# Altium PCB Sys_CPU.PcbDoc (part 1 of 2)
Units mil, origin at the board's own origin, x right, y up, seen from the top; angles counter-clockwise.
Board outline 2999.97 x 2496.97 mil, 4 copper layers (Top Layer, GND, POWER, Bottom Layer); 73 components, 87 nets, 428 pads, 131 vias.
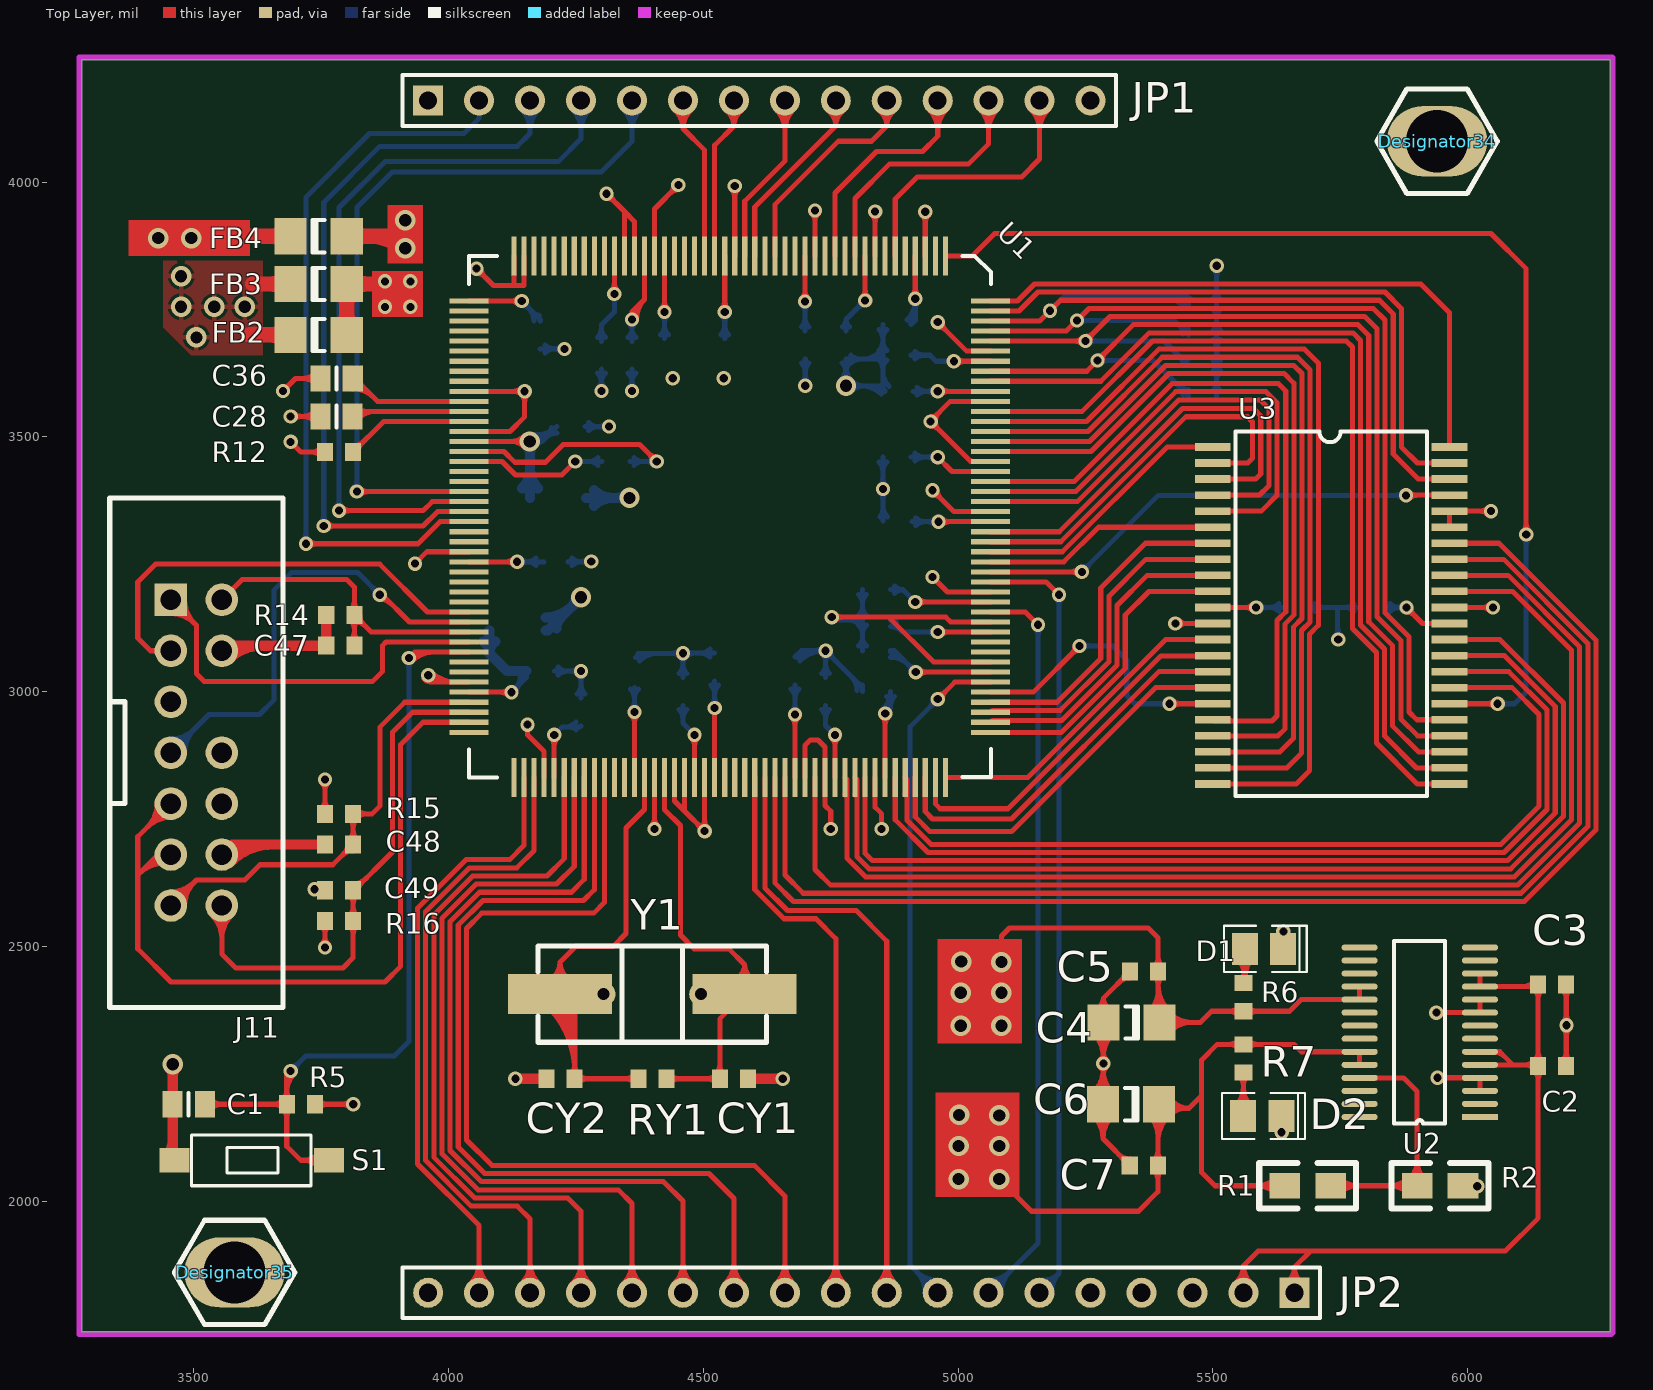
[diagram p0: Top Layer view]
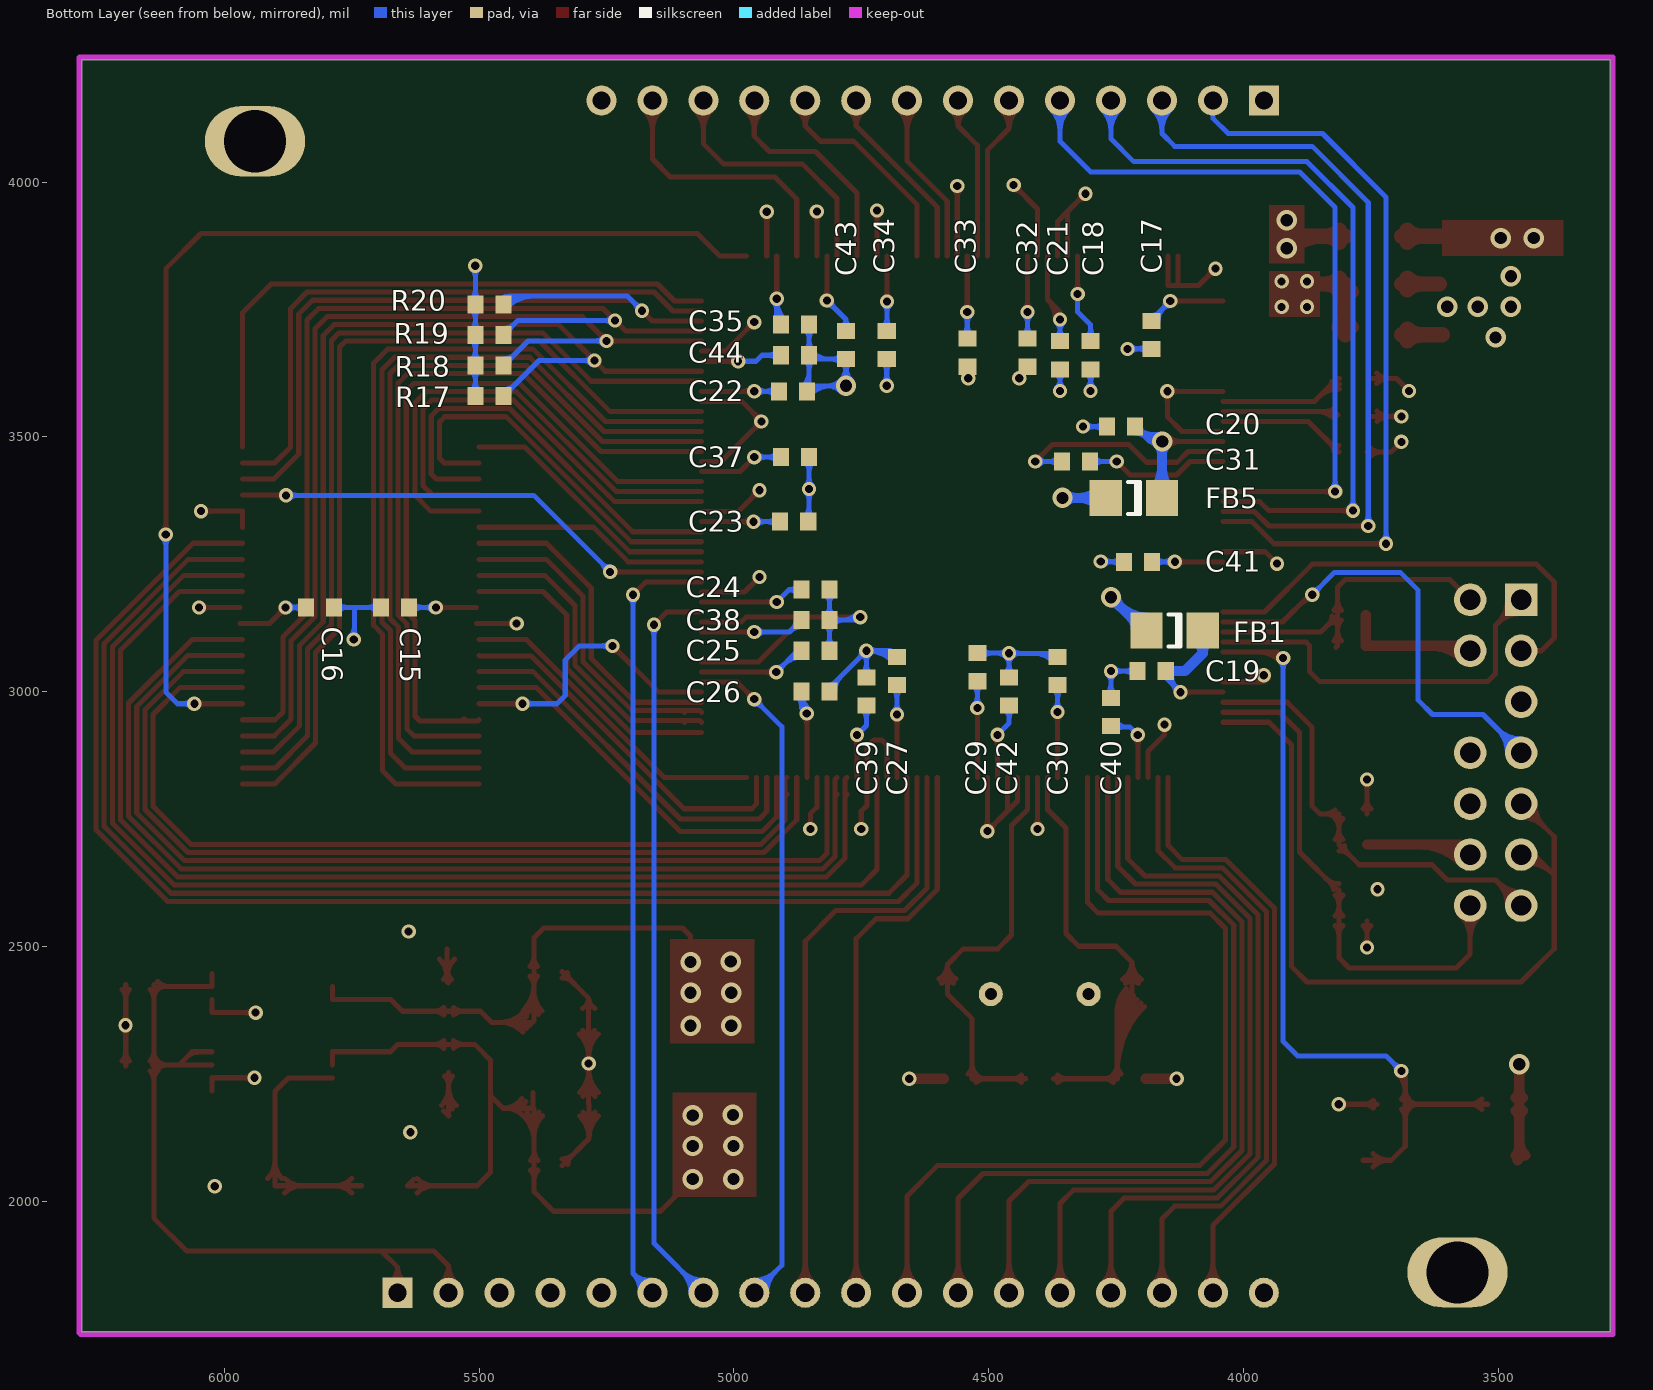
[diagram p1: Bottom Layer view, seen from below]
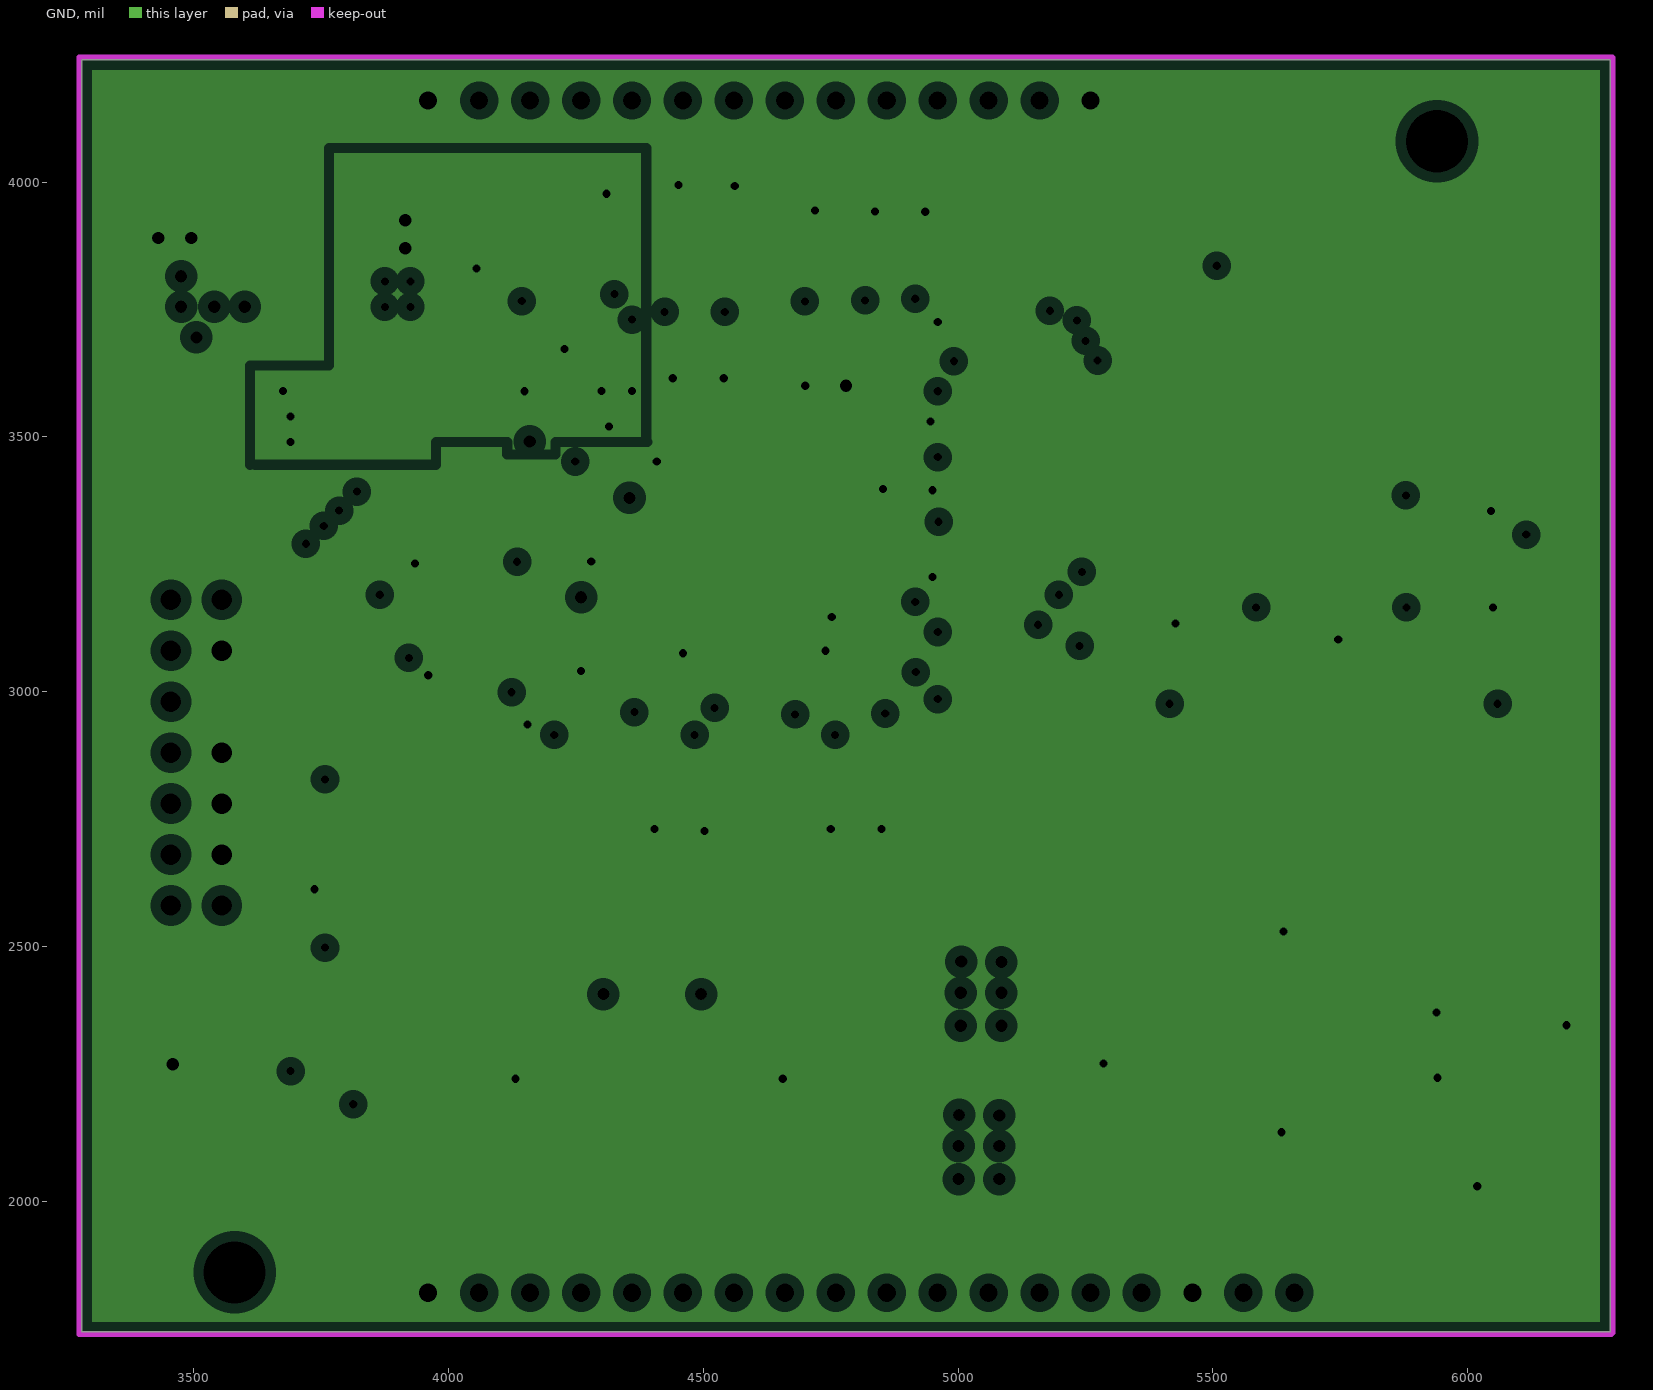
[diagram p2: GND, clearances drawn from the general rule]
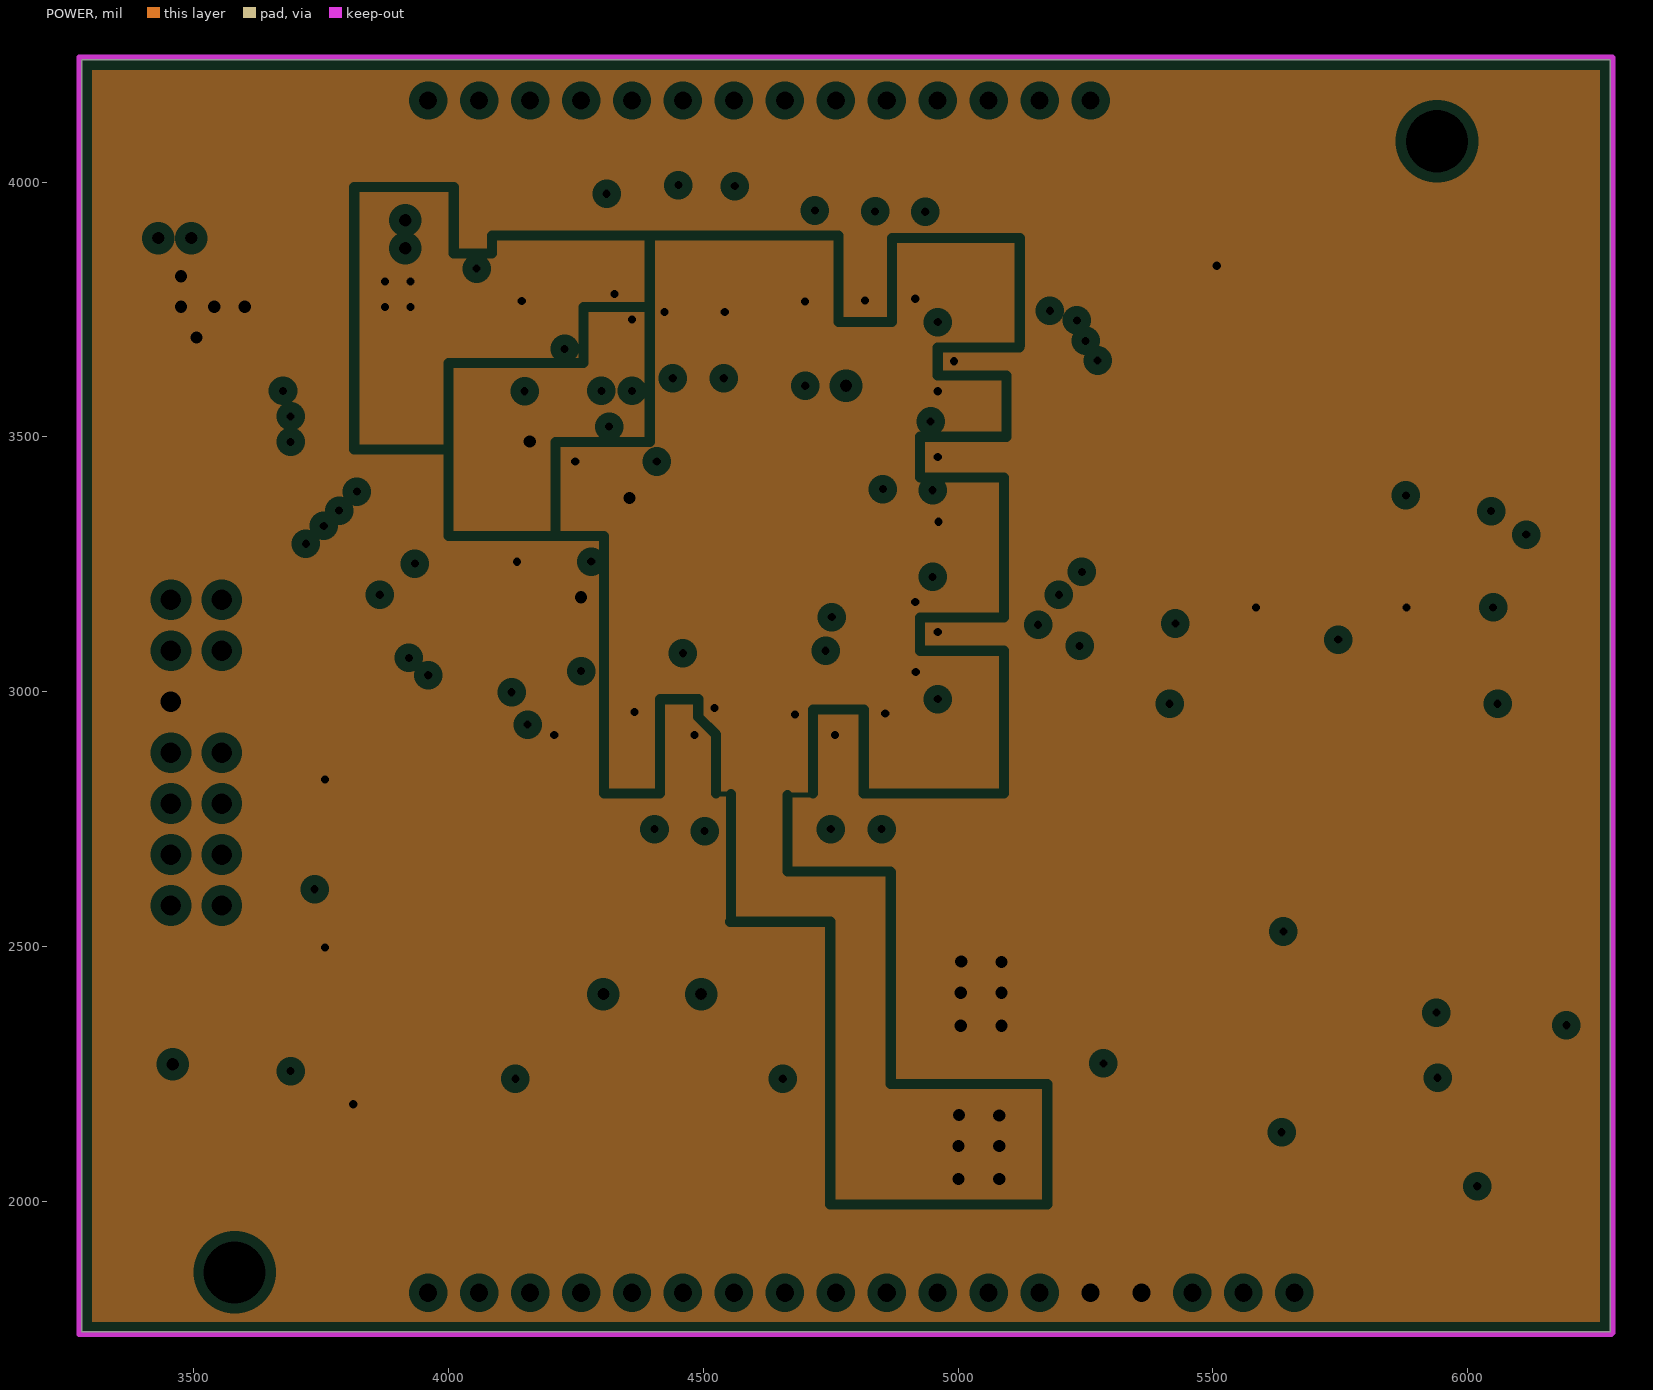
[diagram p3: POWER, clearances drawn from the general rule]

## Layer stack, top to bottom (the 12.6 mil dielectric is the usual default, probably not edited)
Top Layer: signal copper 1.4
Dielectric: core 12.6, FR-4, Dk 4.8
GND: plane copper 1.4, net GND
Dielectric: prepreg 12.6, FR-4, Dk 4.8
POWER: plane copper 1.4, net (Multiple Nets)
Dielectric: core 12.6, FR-4, Dk 4.8
Bottom Layer: signal copper 1.4

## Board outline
3280.01,1743.02 3280.01,4239.98 6279.98,4239.98 6279.98,1743.08 6279.92,1743.02

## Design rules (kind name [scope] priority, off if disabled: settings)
Clearance [All] p1: gap=6
ComponentClearance [All] p1 off: gap=10 collisioncheckmode=3 verticalgap=100000 showdistances=TRUE
Height [All] p1 off: minheight=0 maxheight=1000 prefheight=500
PlaneClearance [All] p1: clearance=20
PlaneConnect [All] p1: planeconnectstyle=Relief reliefexpansion=20 reliefentries=4 reliefconductorwidth=10 reliefairgap=10
PolygonConnect [All] p1: connectstyle=Relief reliefconductorwidth=10 reliefentries=4 polygonreliefangle="90 Angle"
RoutingVias [All] p1: holewidth=28 width=50 viastyle="Through Hole" minholewidth=28 minwidth=50 maxholewidth=28 maxwidth=50
SilkscreenOverComponentPads [All] p1: minsilkscreentomaskgap=10
SolderMaskExpansion [All] p1: expansion=4
Width [All] p1: maxlimit=100 minlimit=6 preferedwidth=10 minimp=50.000000 maximp=50.000000 favimp=50.000000
23 further rules are at their usual default settings.

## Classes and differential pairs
component class CONNECTOR: JP1 JP2
component class RAM: C2 C3 C4 C5 C6 C7 C15 C16 R1 R2 U2 U3
component class TMS320F28335: C1 C17 C18 C19 C20 C21 C22 C23 C24 C25 C26 C27 C28 C29 C30 C31 C32 C33 C34 C35 C36 C37 C38 C39 C40 C41 C42 C43 C44 C47 C48 C49 CY1 CY2 D1 D2 FB1 FB2 FB3 FB4 FB5 J11 R5 R6 R7 R12 R14 R15 R16 R17 R18 R19 R20 RY1 S1 U1 Y1

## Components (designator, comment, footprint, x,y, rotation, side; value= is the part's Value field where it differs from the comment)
C1 "Cap" 6-0805_L 3490,2190 r0 top
C2 "0.1uF" 1608[0603] 6166,2265 r180 top
C3 "Cap" 1608[0603] 6166,2425 r180 top
C4 "10uF" 1206 5345.2,2350.69 r180 top
C5 "0.1uF" 0603 5365.2,2450.69 r180 top
C6 "10uF" 1206 5344.44,2190 r180 top
C7 "0.1uF" 0603 5364.44,2070 r180 top
C15 "Cap" 1608[0603] 5665,3165 r180 bottom
C16 "Cap" 1608[0603] 5812.56,3165 r0 bottom
C17 "0.1uF" 1608[0603] 4180,3700 r90 bottom
C18 "0.1uF" 1608[0603] 4300,3660 r90 bottom
C19 "0.1uF" 1608[0603] 4180,3040 r180 bottom
C20 "0.1uF" 1608[0603] 4240,3520 r180 bottom
C21 "0.1uF" 1608[0603] 4360,3660 r90 bottom
C22 "0.1uF" 1608[0603] 4884.25,3589.25 r0 bottom
C23 "0.1uF" 1608[0603] 4881.65,3333.35 r0 bottom
C24 "0.1uF" 1608[0603] 4840,3200 r0 bottom
C25 "0.1uF" 1608[0603] 4840,3080 r0 bottom
C26 "0.1uF" 1608[0603] 4840,3000 r0 bottom
C27 "0.1uF" 1608[0603] 4680,3040 r270 bottom
C28 "Cap" 6-0805_L 3780,3540 r0 top
C29 "0.1uF" 1608[0603] 4522.25,3047.75 r270 bottom
C30 "0.1uF" 1608[0603] 4364.77,3040 r270 bottom
C31 "0.1uF" 1608[0603] 4328.54,3451.46 r180 bottom
C32 "0.1uF" 1608[0603] 4423.82,3665 r90 bottom
C33 "0.1uF" 1608[0603] 4541.93,3665 r90 bottom
C34 "0.1uF" 1608[0603] 4700,3680 r90 bottom
C35 "0.1uF" 1608[0603] 4880,3720 r0 bottom
C36 "Cap" 6-0805_L 3780.43,3614.57 r0 top
C37 "0.1uF" 1608[0603] 4880,3460 r0 bottom
C38 "0.1uF" 1608[0603] 4840,3140 r0 bottom
C39 "0.1uF" 1608[0603] 4740,3000 r270 bottom
C40 "0.1uF" 1608[0603] 4260,2960 r270 bottom
C41 "0.1uF" 1608[0603] 4207.05,3254.61 r180 bottom
C42 "0.1uF" 1608[0603] 4460,3000 r270 bottom
C43 "0.1uF" 1608[0603] 4780,3680 r90 bottom
C44 "0.1uF" 1608[0603] 4880,3660 r0 bottom
C47 "330pF" 1608[0603] 3787.44,3090 r0 top
C48 "0.1uF" 1608[0603] 3785,2700 r0 top
C49 "0.1uF" 1608[0603] 3785,2610 r0 top
CY1 "Cap" 0603 4560,2240 r180 top
CY2 "Cap" 0603 4220,2240 r0 top
D1 "LED3" "SMD _LED" 5600.44,2495 r180 top
D2 "LED3" "SMD _LED" 5597,2167 r180 top
Designator34 "Comment" PLACEHOLE 5940,4080 r0 top
Designator35 "Comment" PLACEHOLE 3580,1860 r0 top
FB1 "Inductor" C1206 4080,3120 r0 bottom
FB2 "Inductor" C1206 3690,3700 r0 top
FB3 "Inductor" C1206 3690,3800 r0 top
FB4 "Inductor" C1206 3690,3893.57 r0 top
FB5 "Inductor" C1206 4160,3380 r0 bottom
J11 "HEADER 7X2" IDC-14 3455,3180 r270 top
JP1 "Header 14" HDR1X14 3960,4160 r0 top
JP2 "Header 18" HDR1X18 5660,1820 r180 top
R1 "100" 0805 5641,2030 r0 top
R2 "30K" 0805 5901,2030 r0 top
R5 "Res1" 1608[0603] 3710,2190 r0 top
R6 "Res1" 1608[0603] 5560,2400 r270 top
R7 "Res1" 1608[0603] 5560,2280 r90 top
R12 "Res1" 1608[0603] 3785,3470 r0 top
R14 "2.2K" 1608[0603] 3787.44,3150 r180 top
R15 "2.2K" 1608[0603] 3785,2760 r0 top
R16 "2.2K" 1608[0603] 3785,2550 r180 top
R17 "Res1" 1608[0603] 5480,3580 r180 bottom
R18 "Res1" 1608[0603] 5480,3640 r180 bottom
R19 "Res1" 1608[0603] 5480,3700 r180 bottom
R20 "Res1" 1608[0603] 5480,3760 r180 bottom
RY1 "Res1" 0603 4400,2240 r0 top
S1 "SW-PB" 3*6*2.5 3765,2080 r180 top
U1 "TMS320F28335" PQFP-176 4975,3855 r270 top
U2 "TPS75701KTT" TPS301 5906,2310 r180 top
U3 "IS61LV51216-10TI" TSOP-44 5500,3480 r0 top
Y1 "XTAL" SMD-CRYSTAL-2POLE 4395,2415 r180 top

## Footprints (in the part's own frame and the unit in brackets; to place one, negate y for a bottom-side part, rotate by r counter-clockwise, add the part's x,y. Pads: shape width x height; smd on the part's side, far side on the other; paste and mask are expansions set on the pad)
3*6*2.5 [mm]
  rect 1.5x1.2 smd: 1(0,0) 2(7.7,0)
  silkscreen extent 0.89,-1.27 6.86,1.27
6-0805_L [mm] "Chip Resistor, Body 2.0x1.2mm, IPC High Density"
  rect 1x1.3 smd: 1(-0.8,0) 2(0.8,0)
  silkscreen extent 0,-0.55 0,0.55, body extent -1.07,-0.7 1.07,0.7, height 0.7
0603 [mm] "Chip Capacitor, Body 1.6x0.8mm, IPC High Density"
  rect 0.8x0.9 smd: 1(-0.7,0) 2(0.7,0)
  body extent -0.87,-0.48 0.87,0.48, height 1.3
0805 [mil]
  rect 60x50 smd: 1(0,0) 2(90,0)
  silkscreen extent -50,-45 140,45
1206 [mm]
  rect 1.6x1.8 smd: 1(-1.273,0) 2(1.527,0)
  silkscreen extent -0.19,-0.8 0.43,0.8
1608[0603] [mm] "Chip Capacitor, Body 1.6x0.8mm, IPC High Density"
  rect 0.8x0.9 smd: 1(-0.7,0) 2(0.7,0)
  body extent -0.87,-0.48 0.87,0.48, height 1.3
C1206 [mm]
  rect 1.6x1.8 smd: 1(-0.003,0) 2(2.797,0)
  silkscreen extent 1.1,-0.8 1.7,0.8
HDR1X14 [mm] "Connector; Header; 14 Position"
  rect 1.5x1.5 hole 0.9: 1(0,0)
  round 1.5 hole 0.9: 2(2.54,0) 3(5.08,0) 4(7.62,0) 5(10.16,0) 6(12.7,0) 7(15.24,0) 8(17.78,0) 9(20.32,0) 10(22.86,0) 11(25.4,0) 12(27.94,0) 13(30.48,0) 14(33.02,0)
  silkscreen extent -1.27,-1.27 34.29,1.27
HDR1X18 [mm] "Connector; Header; 18 Position"
  rect 1.5x1.5 hole 0.9: 1(0,0)
  round 1.5 hole 0.9: 2(2.54,0) 3(5.08,0) 4(7.62,0) 5(10.16,0) 6(12.7,0) 7(15.24,0) 8(17.78,0) 9(20.32,0) 10(22.86,0) 11(25.4,0) 12(27.94,0) 13(30.48,0) 14(33.02,0) 15(35.56,0) 16(38.1,0) 17(40.64,0) 18(43.18,0)
  silkscreen extent -1.27,-1.27 44.45,1.27
IDC-14 [mil]
  rect 64x64 hole 40: 1(0,0)
  round 64 hole 40: 2(0,100) 3(100,0) 4(100,100) 5(200,0) 7(300,0) 8(300,100) 9(400,0) 10(400,100) 11(500,0) 12(500,100) 13(600,0) 14(600,100)
  round 0 all layers, no hole: 6(200,100)
  silkscreen extent -200,-120 800,220
PLACEHOLE [mm]
  oval 5x3.5 hole 3.1: 0(0,0)
  silkscreen extent -3,-2.6 3,2.6
PQFP-176 [mil]
  rect 76x10 smd: 1(0,0) 2(0,-19.68) 3(0,-39.37) 4(0,-59.05) 5(0,-78.74) 6(0,-98.42) 7(0,-118.11) 8(0,-137.79) 9(0,-157.48) 10(0,-177.16) 11(0,-196.85) 12(0,-216.53) 13(0,-236.22) 14(0,-255.9) 15(0,-275.59) 16(0,-295.27) 17(0,-314.96) 18(0,-334.64) 19(0,-354.33) 20(0,-374.01) 21(0,-393.7) 22(0,-413.38) 23(0,-433.07) 24(0,-452.75) 25(0,-472.44) 26(0,-492.12) 27(0,-511.81) 28(0,-531.49) 29(0,-551.18) 30(0,-570.86) 31(0,-590.55) 32(0,-610.23) 33(0,-629.92) 34(0,-649.6) 35(0,-669.29) 36(0,-688.97) 37(0,-708.66) 38(0,-728.34) 39(0,-748.03) 40(0,-767.71) 41(0,-787.4) 42(0,-807.08) 43(0,-826.77) 44(0,-846.45) 89(1023.62,-846.45) 90(1023.62,-826.77) 91(1023.62,-807.08) 92(1023.62,-787.4) 93(1023.62,-767.71) 94(1023.62,-748.03) 95(1023.62,-728.34) 96(1023.62,-708.66) 97(1023.62,-688.97) 98(1023.62,-669.29) 99(1023.62,-649.6) 100(1023.62,-629.92) 101(1023.62,-610.23) 102(1023.62,-590.55) 103(1023.62,-570.86) 104(1023.62,-551.18) 105(1023.62,-531.49) 106(1023.62,-511.81) 107(1023.62,-492.12) 108(1023.62,-472.44) 109(1023.62,-452.75) 110(1023.62,-433.07) 111(1023.62,-413.38) 112(1023.62,-393.7) 113(1023.62,-374.01) 114(1023.62,-354.33) 115(1023.62,-334.64) 116(1023.62,-314.96) 117(1023.62,-295.27) 118(1023.62,-275.59) 119(1023.62,-255.9) 120(1023.62,-236.22) 121(1023.62,-216.53) 122(1023.62,-196.85) 123(1023.62,-177.16) 124(1023.62,-157.48) 125(1023.62,-137.79) 126(1023.62,-118.11) 127(1023.62,-98.42) 128(1023.62,-78.74) 129(1023.62,-59.05) 130(1023.62,-39.37) 131(1023.62,-19.68) 132(1023.62,0)
  rect 10x76 smd: 45(88.58,-935.04) 46(108.27,-935.04) 47(127.95,-935.04) 48(147.64,-935.04) 49(167.32,-935.04) 50(187.01,-935.04) 51(206.69,-935.04) 52(226.38,-935.04) 53(246.06,-935.04) 54(265.75,-935.04) 55(285.43,-935.04) 56(305.12,-935.04) 57(324.8,-935.04) 58(344.49,-935.04) 59(364.17,-935.04) 60(383.86,-935.04) 61(403.54,-935.04) 62(423.23,-935.04) 63(442.91,-935.04) 64(462.6,-935.04) 65(482.28,-935.04) 66(501.97,-935.04) 67(521.65,-935.04) 68(541.34,-935.04) 69(561.02,-935.04) 70(580.71,-935.04) 71(600.39,-935.04) 72(620.08,-935.04) 73(639.76,-935.04) 74(659.45,-935.04) 75(679.13,-935.04) 76(698.82,-935.04) 77(718.5,-935.04) 78(738.19,-935.04) 79(757.87,-935.04) 80(777.56,-935.04) 81(797.24,-935.04) 82(816.93,-935.04) 83(836.61,-935.04) 84(856.3,-935.04) 85(875.98,-935.04) 86(895.67,-935.04) 87(915.35,-935.04) 88(935.04,-935.04) 133(935.04,88.58) 134(915.35,88.58) 135(895.67,88.58) 136(875.98,88.58) 137(856.3,88.58) 138(836.61,88.58) 139(816.93,88.58) 140(797.24,88.58) 141(777.56,88.58) 142(757.87,88.58) 143(738.19,88.58) 144(718.5,88.58) 145(698.82,88.58) 146(679.13,88.58) 147(659.45,88.58) 148(639.76,88.58) 149(620.08,88.58) 150(600.39,88.58) 151(580.71,88.58) 152(561.02,88.58) 153(541.34,88.58) 154(521.65,88.58) 155(501.97,88.58) 156(482.28,88.58) 157(462.6,88.58) 158(442.91,88.58) 159(423.23,88.58) 160(403.54,88.58) 161(383.86,88.58) 162(364.17,88.58) 163(344.49,88.58) 164(324.8,88.58) 165(305.12,88.58) 166(285.43,88.58) 167(265.75,88.58) 168(246.06,88.58) 169(226.38,88.58) 170(206.69,88.58) 171(187.01,88.58) 172(167.32,88.58) 173(147.64,88.58) 174(127.95,88.58) 175(108.27,88.58) 176(88.58,88.58)
  silkscreen extent 0,-935 1024,89
"SMD _LED" [mm] "SMT LED; 2 Leads"
  rect 1.3x1.6 smd: 1(0.95,0) 2(-0.95,0)
  silkscreen extent -2.13,-1.15 2,1.15
SMD-CRYSTAL-2POLE [mm]
  rect 5.2x2 smd: 1(-4.721,0.227) 2(4.479,0.227)
  round 1.2 hole 0.6: 1(-2.561,0.227) 2(2.319,0.227)
  silkscreen extent -5.82,-2.17 5.58,2.63
TPS301 [mm]
  rect 1.8x0.3 smd: 1(-3.005,3.683)
  oval 1.8x0.3 smd: 2(-3.005,3.033) 3(-3.005,2.383) 4(-3.005,1.733) 5(-3.005,1.083) 6(-3.005,0.433) 7(-3.005,-0.217) 8(-3.005,-0.867) 9(-3.005,-1.517) 10(-3.005,-2.167) 11(-3.005,-2.817) 12(-3.005,-3.467) 13(-3.005,-4.117) 14(-3.005,-4.767) 15(2.995,-4.767) 16(2.995,-4.117) 17(2.995,-3.467) 18(2.995,-2.817) 19(2.995,-2.167) 20(2.995,-1.517) 21(2.995,-0.867) 22(2.995,-0.217) 23(2.995,0.433) 24(2.995,1.083) 25(2.995,1.733) 26(2.995,2.383) 27(2.995,3.033) 28(2.995,3.683)
  silkscreen extent -1.27,-5.09 1.27,4.01
TSOP-44 [mil]
  rect 70x15 smd: 1(0,0) 2(0,-31.5) 3(0,-62.99) 4(0,-94.49) 5(0,-125.98) 6(0,-157.48) 7(0,-188.98) 8(0,-220.47) 9(0,-251.97) 10(0,-283.46) 11(0,-314.96) 12(0,-346.46) 13(0,-377.95) 14(0,-409.45) 15(0,-440.95) 16(0,-472.44) 17(0,-503.94) 18(0,-535.43) 19(0,-566.93) 20(0,-598.43) 21(0,-629.92) 22(0,-661.42) 23(464.56,-661.42) 24(464.56,-629.92) 25(464.56,-598.43) 26(464.56,-566.93) 27(464.56,-535.43) 28(464.56,-503.94) 29(464.56,-472.44) 30(464.56,-440.95) 31(464.56,-409.45) 32(464.56,-377.95) 33(464.56,-346.46) 34(464.56,-314.96) 35(464.56,-283.46) 36(464.56,-251.97) 37(464.56,-220.47) 38(464.56,-188.98) 39(464.56,-157.48) 40(464.56,-125.98) 41(464.56,-94.49) 42(464.56,-62.99) 43(464.56,-31.5) 44(464.56,0)
  silkscreen extent 45,-685 420,30

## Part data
C1 C3 C15 C16 C28 C36 CY1 CY2: "Capacitor"
C2 C17 C18 C19 C20 C21 C22 C23 C24 C25 C26 C27 C29 C30 C31 C32 C33 C34 C35 C37 C38 C39 C40 C41 C42 C43 C44 C47 C48 C49: library part Cap, "Capacitor"
C4 C6: library part C
C5 C7: library part C1
D1 D2: "Typical BLUE SiC LED"
JP1: "Header, 14-Pin"
JP2: "Header, 18-Pin"
R1 R2: library part R
R5 R6 R7 R12 R17 R18 R19 R20 RY1: "Resistor"
R14 R15 R16: library part Res1, "Resistor"
S1: "Switch"
U2: library part tps301
U3: library part Component_1_1
Y1: "Crystal Oscillator"

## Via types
v1: diameter 28, hole 16, Top Layer to Bottom Layer, 105 vias
v2: diameter 40, hole 24, Top Layer to Bottom Layer, 25 vias
v3: diameter 40, hole 24, Top Layer to Bottom Layer, tented bottom, 1 vias

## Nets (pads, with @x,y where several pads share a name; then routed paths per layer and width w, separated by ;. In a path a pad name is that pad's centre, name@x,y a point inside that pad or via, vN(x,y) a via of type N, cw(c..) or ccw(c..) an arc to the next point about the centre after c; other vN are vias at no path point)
+1.9V: C6.1 C7.1 C22.2 C23.2 C24.2 C25.2 C26.2 C27.2 C29.2 C30.2 C31.2 C32.2 C33.2 C34.2 C35.2 FB5.2 R1.1 R7.2 U1.4 U1.15 U1.23 U1.29 U1.61 U1.101 U1.109 U1.117 U1.126 U1.139 U1.146 U1.154 U1.167 U2.23 U2.24 | length 5875.7
  Top Layer w10: U1.61@4039.97,3451.46 4105,3451.46 4131.46,3425 4222.08,3425 v1(4248.54,3451.46) ; v1@4358.4,2953.4 cw(c4343.04,2938.04) 4364.77,2938.04 cw(c4386.5,2938.04) v1@4371.13,2953.4 ; U1.101@4364.77,2831.38 v1(4364.77,2959.77) v1@4365,2960 ; v1@4417.46,3751.36 ccw(c4402.1,3766.73) 4423.82,3766.73 ccw(c4445.55,3766.73) v1@4430.19,3751.36 ; v1(4423.82,3745) U1.29@4423.82,3855 ; U1.109@4522.25,2831.38 4522.25,2940 ; 4522.25,2947.25 4522.25,2940 ; v1(4522.25,2967.75) 4522.25,2940 ; v1@4535.57,3751.36 ccw(c4520.21,3766.73) 4541.93,3766.73 ccw(c4563.66,3766.73) v1@4548.3,3751.36 ; v1(4541.93,3745) U1.23@4541.93,3855 ; v1@4673.64,2948.64 cw(c4658.93,2933.93) 4679.73,2933.93 ; U1.117@4679.73,2831.38 4679.73,2954.73 v1(4680,2955) ; 4679.73,2932.62 cw(c4702.38,2932.62) v1@4686.36,2948.64 ; v1@4693.05,3771.95 ccw(c4677.69,3787.31) 4699.41,3787.31 ccw(c4721.14,3787.31) v1@4705.78,3771.95 ; v1(4699.41,3765.59) U1.15@4699.41,3855 ; v1@4850.53,2950.53 cw(c4835.17,2935.17) 4856.89,2935.17 cw(c4878.62,2935.17) v1@4863.26,2950.53 ; U1.126@4856.89,2831.38 v1(4856.89,2956.89) ; v1@4909.58,3777.31 ccw(c4894.22,3792.68) 4915.95,3792.68 ccw(c4937.68,3792.68) v1@4922.31,3777.31 ; v1(4915.87,3175.87) U1.146@5063.59,3175.87 ; v1(4915.95,3770.95) U1.4@4915.95,3855 ; v1(4916.93,3038.07) U1.139@5063.59,3038.07 ; v1@4922.23,3169.5 cw(c4937.6,3154.14) 4937.6,3175.87 cw(c4937.6,3197.6) v1@4922.23,3182.23 ; v1@4923.29,3031.71 cw(c4938.66,3016.34) 4938.66,3038.07 cw(c4938.66,3059.8) v1@4923.29,3044.44 ; v1(4960,3589.25) U1.167@5063.59,3589.25 ; v1(4961.65,3333.35) U1.154@5063.59,3333.35 ; v1@4966.36,3582.89 cw(c4981.73,3567.52) 4981.73,3589.25 cw(c4981.73,3610.98) v1@4966.36,3595.62 ; v1@4968.02,3326.98 cw(c4983.38,3311.62) 4983.38,3333.35 cw(c4983.38,3355.08) v1@4968.02,3339.71 ; v2@5081,2028 cw(c5081,1991.79) 5106.61,2017.39 cw(c5132.21,2043) v2@5096,2043 ; v2(5081,2043) 5144,1980 5354,1980 5392,2018 C7.1@5392,2070 5392,2182.16 5453.16,2182.16 ; C6.1@5375.82,2167.33 cw(c5336.77,2128.27) 5392,2128.27 ; C6.1@5382.89,2174.4 cw(c5360.91,2152.42) 5392,2152.42 ; C7.1@5384.4,2060.43 cw(c5366.05,2042.08) 5392,2042.08 cw(c5417.95,2042.08) C7.1@5399.6,2060.43 ; C7.1@5384.4,2079.57 ccw(c5366.05,2097.92) 5392,2097.92 ccw(c5417.95,2097.92) C7.1@5399.6,2079.57 ; 5392,2115.92 cw(c5464.7,2115.92) 5413.29,2167.33 cw(c5449.12,2131.51) 5449.12,2182.16 ; 5392,2140.06 cw(c5440.56,2140.06) C6.1@5406.22,2174.4 ; C6.1@5394.56,2190 C6.1@5394.56,2212.56 ; C6.1@5408.04,2195.57 ccw(c5433.88,2213.78) 5433.88,2182.16 ; C6.1@5416.22,2201.33 ccw(c5453.16,2227.36) 5453.16,2182.16 ; R7.2@5550.43,2299.96 ccw(c5532.08,2281.61) 5532.08,2307.56 ccw(c5532.08,2333.51) R7.2@5550.43,2315.16 ; R7.2@5569.57,2299.96 cw(c5587.92,2281.61) 5587.92,2307.56 cw(c5587.92,2333.51) R7.2@5569.57,2315.16 ; R1.1@5621.86,2015.86 ccw(c5587.72,1981.72) 5587.72,2030 ccw(c5587.72,2078.28) R1.1@5621.86,2044.14 ; R1.1@5628.56,2042.44 R1.1@5641,2030 5504,2030 5478,2056 5478,2207 ; U2.24@5788.09,2267.36 U2.23@5788.09,2292.95 5674.05,2292.95 5659.44,2307.56 R7.2@5560,2307.56 5508.56,2307.56 5478,2277 5478,2207 ; 5453.16,2182.16 5478,2207
  Bottom Layer w10: v1(4248.54,3451.46) 4275,3451.46 C31.2@4300.98,3451.46 ; C31.2@4293.38,3443.86 ccw(c4275.03,3425.51) 4275.03,3451.46 ccw(c4275.03,3477.41) C31.2@4293.38,3459.06 ; C30.2@4357.17,3004.84 cw(c4338.82,2986.49) 4364.77,2986.49 cw(c4390.72,2986.49) C30.2@4372.37,3004.84 ; v1@4358.4,2966.13 ccw(c4343.04,2981.5) 4364.77,2981.5 ccw(c4386.5,2981.5) v1@4371.13,2966.13 ; v1(4364.77,2959.77) C30.2@4364.77,3007.67 ; C32.2@4416.22,3700.16 ccw(c4397.88,3718.51) 4423.82,3718.51 ccw(c4449.77,3718.51) C32.2@4431.42,3700.16 ; v1@4417.46,3738.64 cw(c4402.1,3723.27) 4423.82,3723.27 cw(c4445.55,3723.27) v1@4430.19,3738.64 ; C32.2@4423.82,3692.56 v1(4423.82,3745) ; C29.2@4514.65,3012.59 cw(c4496.3,2994.24) 4522.25,2994.24 cw(c4548.2,2994.25) C29.2@4529.85,3012.59 ; v1@4515.88,2974.12 ccw(c4500.52,2989.48) 4522.25,2989.48 ccw(c4543.98,2989.48) v1@4528.61,2974.12 ; v1(4522.25,2967.75) C29.2@4522.25,3020.19 ; C33.2@4534.33,3700.16 ccw(c4515.99,3718.51) 4541.93,3718.51 ccw(c4567.88,3718.51) C33.2@4549.53,3700.16 ; v1@4535.57,3738.64 cw(c4520.21,3723.27) 4541.93,3723.27 cw(c4563.66,3723.27) v1@4548.3,3738.64 ; C33.2@4541.93,3692.56 v1(4541.93,3745) ; C27.2@4672.4,3004.84 cw(c4654.05,2986.49) 4680,2986.49 cw(c4705.95,2986.49) C27.2@4687.6,3004.84 ; v1@4673.64,2961.36 ccw(c4658.27,2976.73) 4680,2976.73 ccw(c4701.73,2976.73) v1@4686.36,2961.36 ; v1(4680,2955) C27.2@4680,3012.44 ; C34.2@4692.4,3715.16 ccw(c4675.47,3732.09) 4699.41,3732.09 ; v1@4693.05,3759.22 cw(c4677.69,3743.86) 4699.41,3743.86 cw(c4721.14,3743.86) v1@4705.78,3759.22 ; C34.2@4699.41,3708.15 v1(4699.41,3765.59) ; 4699.41,3734.92 ccw(c4727.36,3734.92) C34.2@4707.6,3715.16 ; v1@4851,2963.69 ccw(c4819.49,3000) C26.2@4867.56,3000 4867.56,2967.56 v1(4856.89,2956.89) ; v1@4857.55,2956.14 ccw(c4838.51,2978.08) 4867.56,2978.08 ; C26.2@4859.96,2990.43 cw(c4841.61,2972.08) 4867.56,2972.08 cw(c4893.51,2972.08) C26.2@4875.16,2990.43 ; C25.2@4867.56,3067.28 cw(c4867.56,3018.62) 4901.97,3053.03 ; C25.2@4867.56,3077.28 cw(c4867.56,3052.76) 4884.9,3070.1 ; C25.2@4867.56,3080 4875,3080 v1(4916.93,3038.07) ; C24.2@4867.56,3200 4891.74,3200 ; C24.2@4875.54,3192.8 cw(c4891.74,3178.18) 4891.74,3200 ; C24.2@4875.54,3207.2 ccw(c4891.74,3221.82) 4891.74,3200 ; C35.2@4899.96,3729.57 ccw(c4861.36,3768.17) v1@4915.95,3768.17 ; C35.2@4907.03,3722.5 ccw(c4885.5,3744.03) 4915.95,3744.03 ; C35.2@4907.56,3720 4915.95,3728.39 v1(4915.95,3770.95) ; v1@4907.93,3038.07 ccw(c4886.2,3038.07) 4901.56,3053.44 ccw(c4916.93,3068.8) v1@4916.93,3047.07 ; C23.2@4909.21,3333.35 v1(4961.65,3333.35) ; v1@4909.58,3764.58 cw(c4894.22,3749.22) 4915.95,3749.22 cw(c4937.68,3749.22) v1@4922.31,3764.58 ; C22.2@4911.81,3589.25 v1(4960,3589.25) ; v1(4915.87,3175.87) 4891.74,3200 ; C23.2@4916.81,3325.75 cw(c4935.16,3307.4) 4935.16,3333.35 cw(c4935.16,3359.3) C23.2@4916.81,3340.95 ; C22.2@4919.41,3581.65 cw(c4937.76,3563.3) 4937.76,3589.25 cw(c4937.76,3615.2) C22.2@4919.41,3596.85 ; v1@4953.64,3582.89 ccw(c4938.27,3567.52) 4938.27,3589.25 ccw(c4938.27,3610.98) v1@4953.64,3595.62 ; v1@4955.29,3326.98 ccw(c4939.92,3311.62) 4939.92,3333.35 ccw(c4939.92,3355.08) v1@4955.29,3339.71
  Bottom Layer w20: FB5.2@4270.12,3380 v2(4355,3380) ; FB5.2@4285.32,3364.8 cw(c4322.01,3328.1) 4322.01,3380 cw(c4322.01,3431.9) FB5.2@4285.32,3395.2 ; v2@4347.93,3372.93 ccw(c4330.86,3355.86) 4330.86,3380 ccw(c4330.86,3404.14) v2@4347.93,3387.07
  other v2: 5001,2043 5001,2108 5081,2108 5081,2168 5002,2169
+1.9VA: C20.2 C21.2 FB5.1 U1.31 U1.59 | length 963.3
  Top Layer w10: U1.59@4039.97,3490.83 v2(4159.17,3490.83) ; v2@4148.57,3480.22 ccw(c4122.96,3454.61) 4122.96,3490.83 ccw(c4122.96,3527.04) v2@4148.57,3501.43 ; v1@4359,3729.97 cw(c4390.3,3731.01) 4368.16,3753.16 ; v1(4360,3730) 4360,3745 4384.45,3769.45 ; v1@4369,3730.3 cw(c4421.84,3732.06) 4384.45,3769.45 ; U1.31@4384.45,3855 4384.45,3769.45
  Bottom Layer w10: v2@4158.08,3485.95 ccw(c4164.83,3516.15) 4186.71,3494.27 ; FB5.1@4159.17,3380.71 FB5.1@4159.88,3380 ; v2(4159.17,3490.83) 4183.27,3490.83 C20.2@4212.44,3520 cw(c4174.22,3558.22) v2@4162.44,3505.47 ; v2@4160.26,3495.71 ccw(c4169.52,3537.18) C20.2@4199.57,3507.13 ; 4190.73,3498.29 cw(c4212.44,3476.58) C20.2@4212.44,3507.28 ; 4195.48,3503.04 ccw(c4180.5,3518.03) C20.2@4201.69,3518.03 ; C21.2@4352.4,3695.16 ccw(c4334.05,3713.51) 4360,3713.51 ccw(c4385.95,3713.51) C21.2@4367.6,3695.16 ; v1@4353.64,3723.64 cw(c4338.27,3708.27) 4360,3708.27 cw(c4381.73,3708.27) v1@4366.36,3723.64 ; C21.2@4360,3687.56 v1(4360,3730)
  Bottom Layer w20: FB5.1@4144.68,3399.14 ccw(c4107.99,3435.83) 4159.88,3435.83 ccw(c4211.78,3435.83) FB5.1@4175.08,3399.14 ; v2@4152.1,3483.76 cw(c4133.32,3464.97) 4159.88,3464.97 ; v2(4159.17,3490.83) 4159.88,3490.12 FB5.1@4159.88,3380 ; 4159.88,3468.4 cw(c4181.6,3468.4) v2@4166.24,3483.76
+3.3V: C4.1 C5.1 C15.2 C16.2 C37.2 C38.2 C39.2 C40.2 C41.2 C42.2 C43.2 C44.2 FB1.2 FB2.1 FB3.1 J11.5 JP2.4 JP2.5 R5.2 R6.2 R15.1 R16.2 R17.1 R18.1 R19.1 R20.1 U1.9 U1.71 U1.93 U1.107 U1.121 U1.143 U1.159 U1.170 U2.18 U2.19 U3.11 U3.33 | length 5501.2
  Top Layer w10: R5.2@3737.56,2190 v1(3813,2190) ; R5.2@3745.16,2182.4 cw(c3763.51,2164.05) 3763.51,2190 cw(c3763.51,2215.95) R5.2@3745.16,2197.6 ; R16.2@3749.84,2540.43 cw(c3731.49,2522.08) 3757.44,2522.08 cw(c3783.39,2522.08) R16.2@3765.04,2540.43 ; R15.1@3749.84,2769.57 ccw(c3731.49,2787.92) 3757.44,2787.92 ccw(c3783.39,2787.92) R15.1@3765.04,2769.57 ; v1@3751.08,2503.92 ccw(c3735.71,2519.29) 3757.44,2519.29 ccw(c3779.17,2519.29) v1@3763.8,2503.92 ; v1@3751.08,2821.2 cw(c3735.71,2805.83) 3757.44,2805.83 cw(c3779.17,2805.83) v1@3763.8,2821.2 ; v1(3757.44,2497.56) R16.2@3757.44,2550 ; R15.1@3757.44,2760 v1(3757.44,2827.56) ; v1@3806.64,2183.64 ccw(c3791.27,2168.27) 3791.27,2190 ccw(c3791.27,2211.73) v1@3806.64,2196.36 ; U1.71@4039.97,3254.61 v1(4134.61,3254.61) ; v1@4128.24,3248.24 ccw(c4112.88,3232.88) 4112.88,3254.61 ccw(c4112.88,3276.34) v1@4128.24,3260.97 ; v1@4200.92,2908.64 cw(c4185.56,2893.27) 4207.29,2893.27 cw(c4229.02,2893.27) v1@4213.65,2908.64 ; U1.93@4207.29,2831.38 v1(4207.29,2915) ; v1@4476.51,2908.64 cw(c4461.15,2893.27) 4482.88,2893.27 cw(c4504.61,2893.27) v1@4489.24,2908.64 ; U1.107@4482.88,2831.38 v1(4482.88,2915) ; v1@4752.1,2908.64 cw(c4736.74,2893.27) 4758.47,2893.27 cw(c4780.2,2893.27) v1@4764.83,2908.64 ; U1.121@4758.47,2831.38 v1(4758.47,2915) ; v1@4811.16,3773.89 ccw(c4795.8,3789.25) 4817.52,3789.25 ccw(c4839.25,3789.25) v1@4823.89,3773.89 ; v1(4817.52,3767.52) U1.9@4817.52,3855 ; v1(4960,3116.81) U1.143@5063.59,3116.81 ; v1(4960,3460) 4988.23,3431.77 U1.159@5063.59,3431.77 ; v1@4966.36,3110.45 cw(c4981.73,3095.08) 4981.73,3116.81 cw(c4981.73,3138.54) v1@4966.36,3123.18 ; v1(4991.69,3648.31) U1.170@5063.59,3648.31 ; v1@4998.06,3641.94 cw(c5013.42,3626.58) 5013.42,3648.31 cw(c5013.42,3670.04) v1@4998.06,3654.67 ; v2@5074.39,2479.61 ccw(c5048.79,2505.21) 5085,2505.21 ccw(c5121.21,2505.21) v2@5095.61,2479.61 ; v2(5085,2469) 5085,2520 5101,2536 5373,2536 5392.75,2516.25 C5.1@5392.75,2450.69 5392.75,2353.25 C4.1@5395.31,2350.69 ; C4.1@5376.58,2373.36 ccw(c5337.53,2412.41) 5392.75,2412.41 ; C4.1@5383.65,2366.29 ccw(c5361.67,2388.27) 5392.75,2388.27 ; C5.1@5385.15,2441.12 cw(c5366.81,2422.77) 5392.75,2422.77 cw(c5418.7,2422.77) C5.1@5400.35,2441.12 ; C5.1@5385.15,2460.25 ccw(c5366.81,2478.6) 5392.75,2478.6 ccw(c5418.7,2478.6) C5.1@5400.35,2460.25 ; 5392.75,2400.63 ccw(c5441.32,2400.63) C4.1@5406.98,2366.29 ; 5392.75,2424.77 ccw(c5465.46,2424.77) C4.1@5414.05,2373.36 ; C4.1@5401.69,2344.31 C4.1@5395.31,2350.69 ; C4.1@5406.98,2339.02 cw(c5435.14,2310.86) 5435.14,2350.69 cw(c5435.14,2390.51) C4.1@5406.98,2362.35 ; C4.1@5414.05,2331.95 cw(c5459.28,2286.72) 5459.28,2350.69 cw(c5459.28,2414.65) C4.1@5414.05,2369.42 ; U3.11@5505,3165.04 v1(5585,3165) v1(5585,3165) ; R6.2@5550.43,2364.84 ccw(c5532.08,2346.49) 5532.08,2372.44 ccw(c5532.08,2398.39) R6.2@5550.43,2380.04 ; 5563.18,3165.04 cw(c5563.18,3143.18) v1@5578.64,3158.64 ; 5563.36,3165.04 ccw(c5563.36,3186.64) v1@5578.64,3171.36 ; R6.2@5569.57,2364.84 cw(c5587.92,2346.49) 5587.92,2372.44 cw(c5587.92,2398.39) R6.2@5569.57,2380.04 ; U2.18@5788.09,2420.91 U2.19@5788.09,2395.31 5673.31,2395.31 5650.44,2372.44 R6.2@5560,2372.44 5497.44,2372.44 5475.69,2350.69 C4.1@5395.31,2350.69 ; v1@5880,3156 cw(c5880,3134.27) 5895.36,3149.64 cw(c5910.73,3165) v1@5889,3165 ; v1(5880,3165) 5911.46,3133.54 U3.33@5969.56,3133.54
  Top Layer w30: 3610,3700 FB2.1@3689.88,3700 ; 3615,3800 FB3.1@3689.88,3800 ; FB2.1@3678.22,3688.34 ccw(c3650.06,3660.18) 3650.06,3700 ccw(c3650.06,3739.82) FB2.1@3678.22,3711.66 ; FB3.1@3678.22,3788.34 ccw(c3650.06,3760.18) 3650.06,3800 ccw(c3650.06,3839.82) FB3.1@3678.22,3811.66
  Bottom Layer w10: v1(4134.61,3254.61) C41.2@4179.49,3254.61 C41.2@4187.05,3254.61 ; v1@4140.97,3248.24 cw(c4156.34,3232.88) 4156.34,3254.61 cw(c4156.34,3276.34) v1@4140.97,3260.97 ; C41.2@4171.89,3247.01 ccw(c4153.54,3228.66) 4153.54,3254.61 ccw(c4153.54,3280.56) C41.2@4171.89,3262.21 ; v1(4207.29,2915) 4222.29,2930 4257.56,2930 C40.2@4260,2932.44 ; 4226.19,2930 ccw(c4226.19,2964.28) C40.2@4250.43,2940.04 ; 4237.98,2930 cw(c4237.98,2912.39) C40.2@4250.43,2924.84 ; C42.2@4452.4,2964.84 cw(c4434.05,2946.49) 4460,2946.49 cw(c4485.95,2946.49) C42.2@4467.6,2964.84 ; C42.2@4460,2972.44 4460,2937.88 v1(4482.88,2915) ; C39.2@4732.4,2964.84 cw(c4714.05,2946.49) 4740,2946.49 cw(c4765.95,2946.49) C39.2@4747.6,2964.84 ; C39.2@4740,2972.44 4740,2933.47 v1(4758.47,2915) ; C43.2@4773.26,3715.93 ccw(c4761.95,3730) 4780,3730 ; C43.2@4780,3707.56 4780,3730 ; C43.2@4786.74,3715.93 cw(c4798.05,3730) 4780,3730 ; v1@4808.52,3767.52 cw(c4786.8,3767.52) 4802.16,3752.16 cw(c4817.52,3736.8) v1@4817.52,3758.52 ; v1(4817.52,3767.52) 4780,3730 ; C38.2@4867.56,3127.28 cw(c4867.56,3096.58) 4889.27,3118.29 ; C38.2@4867.56,3140 4890.75,3116.81 v1(4960,3116.81) ; C38.2@4878.31,3138.03 ccw(c4899.5,3138.03) 4884.52,3123.04 ; C37.2@4907.56,3460 v1(4960,3460) ; C44.2@4907.56,3660 4945,3660 4956.69,3648.31 v1(4991.69,3648.31) ; C37.2@4915.16,3452.4 cw(c4933.51,3434.05) 4933.51,3460 cw(c4933.51,3485.95) C37.2@4915.16,3467.6 ; C44.2@4915.16,3652.4 cw(c4933.51,3634.05) 4933.51,3660 cw(c4933.51,3685.95) C44.2@4915.16,3667.6 ; v1@4953.64,3110.45 ccw(c4938.27,3095.08) 4938.27,3116.81 ccw(c4938.27,3138.54) v1@4953.64,3123.18 ; v1@4953.64,3453.64 ccw(c4938.27,3438.27) 4938.27,3460 ccw(c4938.27,3481.73) v1@4953.64,3466.36 ; R17.1@5499.96,3589.57 ccw(c5481.61,3607.92) 5507.56,3607.92 ccw(c5533.51,3607.92) R17.1@5515.16,3589.57 ; R18.1@5499.96,3630.43 cw(c5481.61,3612.08) 5507.56,3612.08 cw(c5533.51,3612.08) R18.1@5515.16,3630.43 ; R18.1@5499.96,3649.57 ccw(c5481.61,3667.92) 5507.56,3667.92 ccw(c5533.51,3667.92) R18.1@5515.16,3649.57 ; R19.1@5499.96,3690.43 cw(c5481.61,3672.08) 5507.56,3672.08 cw(c5533.51,3672.08) R19.1@5515.16,3690.43 ; R19.1@5499.96,3709.57 ccw(c5481.61,3727.92) 5507.56,3727.92 ccw(c5533.51,3727.92) R19.1@5515.16,3709.57 ; R20.1@5499.96,3750.43 cw(c5481.61,3732.08) 5507.56,3732.08 cw(c5533.51,3732.08) R20.1@5515.16,3750.43 ; R20.1@5499.96,3769.57 ccw(c5481.61,3787.92) 5507.56,3787.92 ccw(c5533.51,3787.92) R20.1@5515.16,3769.57 ; v1@5501.2,3829.2 cw(c5485.83,3813.83) 5507.56,3813.83 cw(c5529.29,3813.83) v1@5513.92,3829.2 ; R17.1@5507.56,3580 R18.1@5507.56,3640 R19.1@5507.56,3700 R20.1@5507.56,3760 v1(5507.56,3835.56) ; v1(5585,3165) C15.2@5637.44,3165 ; v1@5591.36,3158.64 cw(c5606.73,3143.27) 5606.73,3165 cw(c5606.73,3186.73) v1@5591.36,3171.36 ; C15.2@5629.84,3157.4 ccw(c5611.49,3139.05) 5611.49,3165 ccw(c5611.49,3190.95) C15.2@5629.84,3172.6 ; C16.2@5840.12,3165 v1(5880,3165) ; C16.2@5847.72,3157.4 cw(c5866.07,3139.05) 5866.07,3165 cw(c5866.07,3190.95) C16.2@5847.72,3172.6 ; v1@5873.64,3158.64 ccw(c5858.27,3143.27) 5858.27,3165 ccw(c5858.27,3186.73) v1@5873.64,3171.36
  Bottom Layer w20: FB1.2@4190.12,3120 4195,3120 v2(4260,3185) v2@4255.12,3185 ; FB1.2@4190.12,3145.43 ccw(c4190.12,3218.62) 4241.87,3166.87 ; FB1.2@4211.61,3123.94 cw(c4242.22,3123.94) FB1.2@4220.58,3145.58 ; v2@4250,3185 cw(c4225.86,3185) 4242.93,3167.93 cw(c4260,3150.86) v2@4260,3175
  other v2: 5005,2344 5085,2344 5005,2409 5085,2409 5006,2470 3505,3695 3475,3755 3540,3755 3600,3755 3475,3815
+3.3VA: C17.2 C18.2 FB2.2 FB3.2 U1.34 U1.45 | length 867
  Top Layer w10: U1.45@4039.97,3766.42 v1(4143.58,3766.42) ; v1@4137.22,3760.05 ccw(c4121.85,3744.69) 4121.85,3766.42 ccw(c4121.85,3788.15) v1@4137.22,3772.78 ; v1@4319.03,3786.36 ccw(c4303.67,3801.73) 4325.4,3801.73 ccw(c4347.13,3801.73) v1@4331.76,3786.36 ; v1(4325.4,3780) U1.34@4325.4,3855
  Top Layer w30: FB2.2@3788.45,3715.6 ccw(c3760.29,3743.76) 3800.12,3743.76 ccw(c3839.94,3743.76) FB2.2@3811.78,3715.6 ; FB3.2@3788.45,3784.4 cw(c3760.29,3756.24) 3800.12,3756.24 cw(c3839.94,3756.24) FB3.2@3811.78,3784.4 ; FB2.2@3800.12,3700 FB3.2@3800.12,3800 3860,3800 ; FB3.2@3811.78,3788.34 cw(c3839.94,3760.18) 3839.94,3800 cw(c3839.94,3839.82) FB3.2@3811.78,3811.66
  Bottom Layer w10: v1@4143.58,3757.42 cw(c4143.58,3735.69) 4158.95,3751.05 cw(c4174.31,3766.42) v1@4152.58,3766.42 ; v1(4143.58,3766.42) 4180,3730 C17.2@4180,3727.56 ; 4156.57,3753.43 cw(c4130.69,3727.56) C17.2@4167.28,3727.56 ; C17.2@4167.21,3742.79 ccw(c4178.03,3753.61) C17.2@4178.03,3738.31 ; C18.2@4292.4,3695.16 ccw(c4274.05,3713.51) 4300,3713.51 ccw(c4325.95,3713.51) C18.2@4307.6,3695.16 ; C18.2@4300,3687.56 4300,3720 4325.4,3745.4 v1(4325.4,3780)
  other v1: 3875,3755 3925,3755 3875,3805 3925,3805
AGND: C17.1 C18.1 C20.1 C21.1 C28.1 C36.1 FB4.2 R12.1 U1.32 U1.33 U1.43 U1.44 U1.54 U1.58 | length 1988.3
  Top Layer w10: v1(3675,3590) 3699.57,3614.57 C36.1@3748.94,3614.57 ; v1(3690,3490) 3710,3470 R12.1@3757.44,3470 ; v1(3690,3540) C28.1@3748.5,3540 ; v1@3696.36,3533.64 cw(c3711.73,3518.27) 3711.73,3540 cw(c3711.73,3561.73) v1@3696.36,3546.36 ; C28.1@3738.12,3529.62 ccw(c3713.05,3504.55) 3713.05,3540 ccw(c3713.05,3575.45) C28.1@3738.12,3550.38 ; C36.1@3738.55,3604.18 ccw(c3713.48,3579.12) 3713.48,3614.57 ccw(c3713.48,3650.02) C36.1@3738.55,3624.95 ; R12.1@3749.84,3462.4 ccw(c3731.49,3444.05) 3731.49,3470 ccw(c3731.49,3495.95) R12.1@3749.84,3477.6 ; U1.58@4039.97,3510.51 4120.51,3510.51 4149.25,3539.25 v1(4149.25,3589.25) U1.54@4039.97,3589.25 ; v1@4055,3821 cw(c4055,3799.27) 4070.36,3814.64 cw(c4085.73,3830) v1@4064,3830 ; v1(4055,3830) 4088.23,3796.77 4130,3796.77 ; U1.44@4128.55,3855 4128.55,3798.22 4130,3796.77 ; v1@4142.89,3595.62 cw(c4127.52,3610.98) 4127.52,3589.25 cw(c4127.52,3567.52) 4142.89,3582.89 cw(c4127.52,3567.52) 4149.25,3567.52 cw(c4170.98,3567.52) v1@4155.62,3582.89 ; U1.43@4148.23,3855 4148.23,3796.77 4130,3796.77 ; v1@4310,3968 cw(c4310,3946.27) 4325.36,3961.64 cw(c4340.73,3977) v1@4319,3977 ; v1(4310,3977) 4345.08,3941.92 ; U1.33@4345.08,3855 4345.08,3941.92 ; U1.32@4364.77,3855 4364.77,3922.23 4345.08,3941.92
  Top Layer w30: FB4.2@3800.12,3893.57 3891.43,3893.57 3895,3890 ; FB4.2@3811.78,3881.9 cw(c3839.94,3853.74) 3839.94,3893.57 cw(c3839.94,3933.39) FB4.2@3811.78,3905.23 ; 3846.03,3893.57 cw(c3846.03,3801.03) v3@3911.46,3866.46
  Bottom Layer w10: C17.1@4180,3672.44 v1(4227.56,3672.44) ; C17.1@4189.57,3664.84 cw(c4207.92,3646.49) 4207.92,3672.44 cw(c4207.92,3698.39) C17.1@4189.57,3680.04 ; v1@4221.2,3666.08 ccw(c4205.83,3650.71) 4205.83,3672.44 ccw(c4205.83,3694.17) v1@4221.2,3678.8 ; C20.1@4267.56,3520 v1(4315,3520) ; C20.1@4275.16,3512.4 cw(c4293.51,3494.05) 4293.51,3520 cw(c4293.51,3545.95) C20.1@4275.16,3527.6 ; C18.1@4292.4,3624.84 cw(c4274.05,3606.49) 4300,3606.49 cw(c4325.95,3606.49) C18.1@4307.6,3624.84 ; v1@4293.64,3596.36 ccw(c4278.27,3611.73) 4300,3611.73 ccw(c4321.73,3611.73) v1@4306.36,3596.36 ; v1(4300,3590) 4300,3605 C18.1@4300,3632.44 ; v1@4308.64,3513.64 ccw(c4293.27,3498.27) 4293.27,3520 ccw(c4293.27,3541.73) v1@4308.64,3526.36 ; C21.1@4352.4,3624.84 cw(c4334.05,3606.49) 4360,3606.49 cw(c4385.95,3606.49) C21.1@4367.6,3624.84 ; v1@4353.64,3596.36 ccw(c4338.27,3611.73) 4360,3611.73 ccw(c4381.73,3611.73) v1@4366.36,3596.36 ; v1(4360,3590) C21.1@4360,3632.44
  other v2: 3915,3925
  other v3: 3915,3870
EMU0: C48.2 J11.13 R15.2 U1.85 | length 1206.1
  Top Layer w10: J11.13@3455,2580 3505,2630 3600,2630 3630,2660 3772.56,2660 C48.2@3812.56,2700 R15.2@3812.56,2760 3850,2760 3865,2775 3865,2930 3914.02,2979.02 U1.85@4039.97,2979.02 ; J11.13@3455,2597 ccw(c3455,2638.04) 3484.02,2609.02 ccw(c3513.04,2580) J11.13@3472,2580 ; J11.13@3455,2607 ccw(c3455,2672.18) 3501.09,2626.09 ccw(c3547.18,2580) J11.13@3482,2580 ; 3790.85,2678.29 cw(c3812.56,2656.58) C48.2@3812.56,2687.28 ; 3795.6,2683.04 ccw(c3780.62,2698.03) C48.2@3801.81,2698.03 ; C48.2@3804.96,2709.57 ccw(c3786.61,2727.92) 3812.56,2727.92 ccw(c3838.51,2727.92) C48.2@3820.16,2709.57 ; R15.2@3804.96,2750.43 cw(c3786.61,2732.08) 3812.56,2732.08 cw(c3838.51,2732.08) R15.2@3820.16,2750.43 ; R15.2@3820.16,2752.4 cw(c3838.51,2734.05) 3838.51,2760 cw(c3838.51,2785.95) R15.2@3820.16,2767.6
EMU1: C49.2 J11.14 R16.1 U1.86 | length 1344.3
  Top Layer w10: J11.14@3535.91,2560.91 cw(c3489.82,2514.82) 3555,2514.82 cw(c3620.18,2514.82) J11.14@3574.09,2560.91 ; J11.14@3542.98,2567.98 cw(c3513.96,2538.96) 3555,2538.96 cw(c3596.04,2538.96) J11.14@3567.02,2567.98 ; J11.14@3555,2580 3555,2485 3582.44,2457.56 3792.56,2457.56 3812.56,2477.56 R16.1@3812.56,2550 C49.2@3812.56,2610 3815,2610 3890,2685 3890,2920 3929.33,2959.33 U1.86@4039.97,2959.33 ; R16.1@3804.96,2540.43 cw(c3786.61,2522.08) 3812.56,2522.08 cw(c3838.51,2522.08) R16.1@3820.16,2540.43 ; R16.1@3804.96,2559.57 ccw(c3786.61,2577.92) 3812.56,2577.92 ccw(c3838.51,2577.92) R16.1@3820.16,2559.57 ; C49.2@3804.96,2600.43 cw(c3786.61,2582.08) 3812.56,2582.08 cw(c3838.51,2582.08) C49.2@3820.16,2600.43 ; C49.2@3812.56,2622.72 ccw(c3812.56,2659.31) 3838.43,2633.43 ; C49.2@3823.31,2611.97 cw(c3838.61,2611.97) C49.2@3827.79,2622.79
